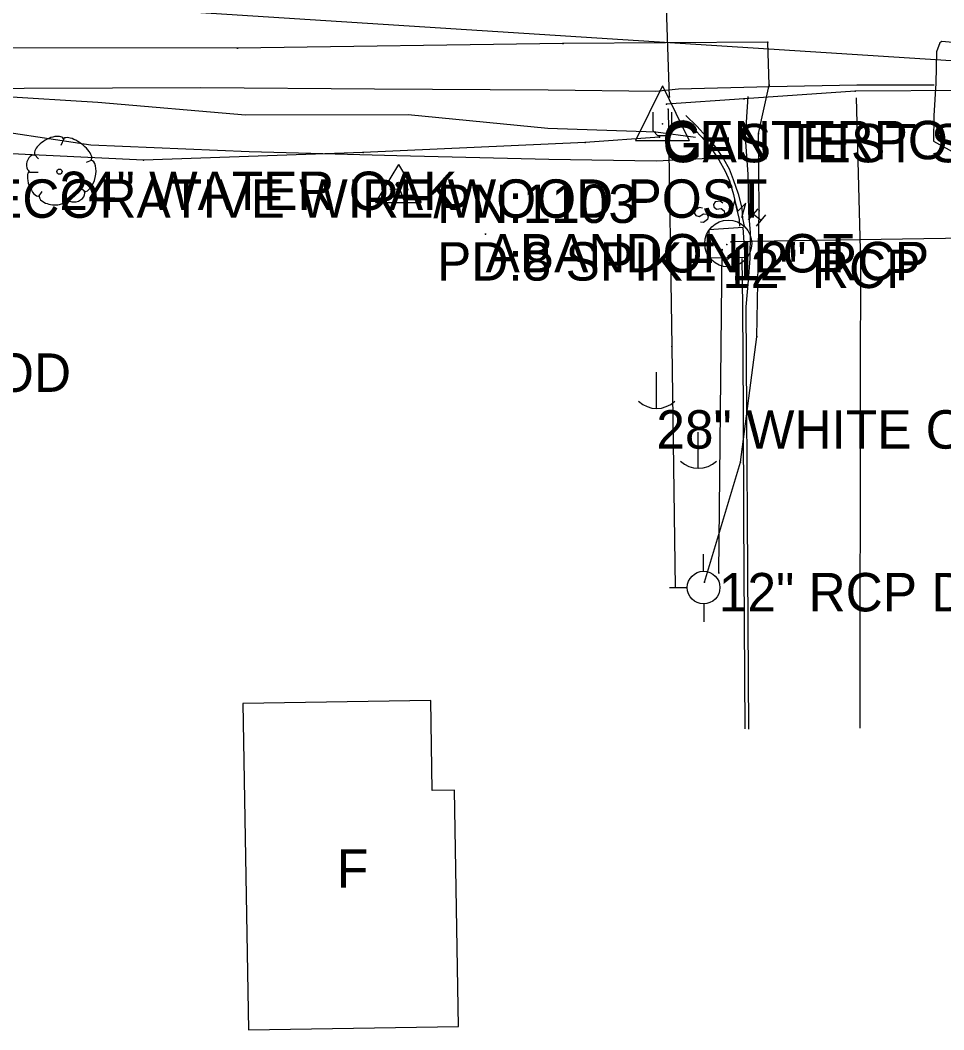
# Model space of a CAD drawing. Extents: x 1304270 to 1306561, y 1876019 to 1876752.
# Drawn here: x 1305816.1 to 1305936.2, y 1876269 to 1876400.4 of the extents above; entities that cross this region are included whole.
import ezdxf

# ---------------------------------------------------------------- set-up
doc = ezdxf.new("R2010")
doc.units = 0
for name, color, linetype in [('Default', 7, 'Continuous'), ('S_BUILDING', 7, 'Continuous'), ('S_BUILDING_ANNOT', 7, 'Continuous'), ('S_CURB', 7, 'Continuous'), ('S_DRG_PT_SYM', 7, 'Continuous'), ('S_EDGE_CONCRETE', 7, 'Continuous'), ('S_EDGE_PAVEMENT', 7, 'Continuous'), ('S_FENCE_ANNOT', 7, 'Continuous'), ('S_FIBER_OPTIC_CABLE', 7, 'Continuous'), ('S_GAS_UTILITIES', 7, 'Continuous'), ('S_MANHOLE', 7, 'Continuous'), ('S_MISC_STRUCTURES_ANNOT', 7, 'Continuous'), ('S_MSC_PT_SYM', 7, 'Continuous'), ('S_PAVEMENT_CROWN', 7, 'Continuous'), ('S_SECONDARY_CTL', 7, 'Continuous'), ('S_SECONDARY_CTL_ANNOT', 7, 'Continuous'), ('S_STORM_SEWER', 7, 'Continuous'), ('S_STORM_SEWER_ANNOT', 7, 'Continuous'), ('S_SURVEY_TEXT_ANNOT', 7, 'Continuous'), ('S_TRAILS', 7, 'Continuous'), ('S_TREE', 7, 'Continuous'), ('S_TREE_ANNOT', 7, 'Continuous'), ('S_UTILITY_POLE', 7, 'Continuous'), ('S_UTILITY_POLE_ANNOT', 7, 'Continuous'), ('S_UTL_PT_SYM', 7, 'Continuous')]:
    doc.layers.add(name, color=color, linetype=linetype)

msp = doc.modelspace()

# ---------------------------------------------------------------- linework, layer by layer
at = {"layer": 'Default'}
msp.add_line((1305473.53, 1876424.94), (1305993.25, 1876391.55), dxfattribs=at)
at = {"layer": 'S_BUILDING'}
msp.add_lwpolyline([(1305845.03, 1876311.46), (1305845.74, 1876269.01), (1305873.08, 1876269.46), (1305872.58, 1876300.2), (1305869.66, 1876300.16), (1305869.47, 1876311.86)], close=True, dxfattribs=at)
at = {"layer": 'S_CURB'}
for points in [[(1305902.26, 1876387.4), (1305903.79, 1876386.18), (1305904.8, 1876385.11), (1305906.11, 1876383.54), (1305906.97, 1876382.21), (1305907.78, 1876380.73), (1305908.35, 1876379.48), (1305908.86, 1876377.7), (1305909.26, 1876375.86), (1305909.61, 1876374.52), (1305909.64, 1876373.6)], [(1305909.96, 1876369.37), (1305910.04, 1876363.22), (1305910.11, 1876349.45), (1305910.19, 1876335.69), (1305910.27, 1876321.92), (1305910.34, 1876308.16)]]:
    msp.add_lwpolyline(points, dxfattribs=at)
at = {"layer": 'S_DRG_PT_SYM'}
msp.add_lwpolyline([(1305910.39, 1876371.51), (1305910.39, 1876371.56), (1305910.39, 1876371.51), (1305910.34, 1876371.51), (1305910.39, 1876371.51), (1305910.39, 1876371.46), (1305910.39, 1876371.51), (1305910.44, 1876371.51)], dxfattribs=at)
at = {"layer": 'S_EDGE_CONCRETE'}
msp.add_lwpolyline([(1305940.34, 1876397.25), (1305935.98, 1876397.61), (1305935.7, 1876397.43), (1305935.28, 1876396.27), (1305935.22, 1876392.2), (1305934.94, 1876387.94), (1305934.88, 1876384.67), (1305937.71, 1876383.09)], dxfattribs=at)
msp.add_lwpolyline([(1305910.11, 1876373.4), (1305905.65, 1876373.1), (1305905.71, 1876369.49), (1305910.41, 1876369.58)], close=True, dxfattribs=at)
at = {"layer": 'S_EDGE_PAVEMENT'}
for points in [[(1305613.53, 1876391.75), (1305628.13, 1876391.53), (1305636.57, 1876391.38), (1305646.7, 1876391.57), (1305664.4, 1876391.37), (1305677.09, 1876391.42), (1305689.77, 1876391.47), (1305705.71, 1876391.48), (1305716.06, 1876391.37), (1305738.42, 1876391.47), (1305752.22, 1876391.48), (1305766.03, 1876391.49), (1305779.83, 1876391.49), (1305793.63, 1876391.5), (1305816.58, 1876391.56), (1305839.54, 1876391.62), (1305862.15, 1876391.47), (1305884.77, 1876391.33), (1305898.76, 1876391.18), (1305901.73, 1876391.47), (1305913.59, 1876391.75), (1305924.92, 1876391.98), (1305934.98, 1876391.98)], [(1305910.73, 1876390.48), (1305910.4, 1876385.14), (1305910.72, 1876380.38), (1305910.82, 1876375.33), (1305911.03, 1876372.76), (1305910.98, 1876369.39), (1305910.79, 1876366.53), (1305910.47, 1876363.11), (1305910.56, 1876349.36), (1305910.65, 1876335.62), (1305910.74, 1876321.87), (1305910.83, 1876308.13)], [(1305902.68, 1876387.99), (1305904.09, 1876386.6), (1305905.37, 1876385.2), (1305906.55, 1876383.89), (1305907.58, 1876382.36), (1305908.3, 1876381.05), (1305908.85, 1876379.67), (1305909.47, 1876377.81), (1305909.94, 1876375.93), (1305910.06, 1876374.57), (1305910.25, 1876373.61)]]:
    msp.add_lwpolyline(points, dxfattribs=at)
at = {"layer": 'S_FIBER_OPTIC_CABLE'}
for p, q in [((1305844.31, 1876396.74), (1305789.79, 1876396.84)), ((1305886.69, 1876397.37), (1305844.31, 1876396.74)), ((1305913.35, 1876397.55), (1305886.69, 1876397.37)), ((1305913.53, 1876391.96), (1305913.35, 1876397.55)), ((1305912.14, 1876385.64), (1305913.53, 1876391.96)), ((1305912.19, 1876375.58), (1305912.14, 1876385.64)), ((1305911.92, 1876359.21), (1305912.19, 1876375.58)), ((1305909.78, 1876342.89), (1305911.92, 1876359.21)), ((1305905.08, 1876327.25), (1305909.78, 1876342.89))]:
    msp.add_line(p, q, dxfattribs=at)
at = {"layer": 'S_GAS_UTILITIES'}
for p, q in [((1305900.53, 1876390.42), (1305899.88, 1876409.72)), ((1305910.24, 1876390.16), (1305900.15, 1876389.47)), ((1305924.69, 1876391.17), (1305910.24, 1876390.16)), ((1305943.66, 1876391.26), (1305924.69, 1876391.17)), ((1305900.37, 1876388.82), (1305900.85, 1876357.93)), ((1305899.24, 1876385.19), (1305889.57, 1876384.49)), ((1305889.57, 1876384.49), (1305860.69, 1876383.2)), ((1305832.09, 1876382.18), (1305808.21, 1876383.3)), ((1305860.69, 1876383.2), (1305832.09, 1876382.18)), ((1305900.85, 1876357.93), (1305901.27, 1876326.56))]:
    msp.add_line(p, q, dxfattribs=at)
at = {"layer": 'S_MANHOLE'}
for p, q in [((1305903.86, 1876375.64), (1305903.78, 1876375.25)), ((1305904.4, 1876376.03), (1305903.86, 1876375.64)), ((1305904.83, 1876375.95), (1305904.4, 1876376.03)), ((1305910.84, 1876374.4), (1305912.08, 1876375.87)), ((1305903.78, 1876375.25), (1305903.98, 1876374.98)), ((1305903.98, 1876374.98), (1305904.4, 1876374.86)), ((1305904.4, 1876374.86), (1305904.95, 1876375.21)), ((1305904.95, 1876375.21), (1305905.41, 1876375.14)), ((1305905.49, 1876374.44), (1305904.95, 1876374.05)), ((1305905.41, 1876375.14), (1305905.57, 1876374.86)), ((1305905.57, 1876374.86), (1305905.49, 1876374.44)), ((1305911.49, 1876375.17), (1305912.46, 1876374.36)), ((1305913.04, 1876375.06), (1305911.8, 1876373.59)), ((1305904.95, 1876374.05), (1305904.56, 1876374.13))]:
    msp.add_line(p, q, dxfattribs=at)
for points in [[(1305907.5, 1876376.57), (1305907.15, 1876376.84), (1305906.5, 1876376.76), (1305906.26, 1876376.41), (1305906.3, 1876376.1), (1305906.65, 1876375.79), (1305907.27, 1876375.91), (1305907.66, 1876375.6), (1305907.7, 1876375.29), (1305907.43, 1876374.9), (1305906.81, 1876374.83), (1305906.46, 1876375.1)], [(1305909.94, 1876374.71), (1305910.49, 1876376.57), (1305909.44, 1876375.56), (1305909.05, 1876377), (1305908.51, 1876375.14)]]:
    msp.add_lwpolyline(points, dxfattribs=at)
msp.add_circle((1305908.19, 1876371.34), 3.05, dxfattribs=at)
at = {"layer": 'S_MSC_PT_SYM'}
for points in [[(1305899.64, 1876386.9), (1305899.64, 1876386.95), (1305899.64, 1876386.9), (1305899.59, 1876386.9), (1305899.64, 1876386.9), (1305899.64, 1876386.85), (1305899.64, 1876386.9), (1305899.69, 1876386.9)], [(1305876.61, 1876372.57), (1305876.61, 1876372.62), (1305876.61, 1876372.57), (1305876.56, 1876372.57), (1305876.61, 1876372.57), (1305876.61, 1876372.52), (1305876.61, 1876372.57), (1305876.66, 1876372.57)]]:
    msp.add_lwpolyline(points, dxfattribs=at)
at = {"layer": 'S_PAVEMENT_CROWN'}
msp.add_lwpolyline([(1305924.84, 1876390.29), (1305925.4, 1876368.9), (1305925.37, 1876353.74), (1305925.35, 1876338.58), (1305925.32, 1876323.41), (1305925.3, 1876308.25)], dxfattribs=at)
at = {"layer": 'S_SECONDARY_CTL'}
for p, q in [((1305865.29, 1876381.62), (1305862.28, 1876376.66)), ((1305865.29, 1876381.62), (1305868.24, 1876376.66)), ((1305862.28, 1876376.66), (1305868.24, 1876376.66))]:
    msp.add_line(p, q, dxfattribs=at)
for radius in [0.311, 0.183, 0.103]:
    msp.add_circle((1305865.29, 1876379.01), radius, dxfattribs=at)
at = {"layer": 'S_STORM_SEWER'}
for p, q in [((1305940.67, 1876372.04), (1305908.55, 1876371.55)), ((1305906.97, 1876328.46), (1305907.41, 1876370.54))]:
    msp.add_line(p, q, dxfattribs=at)
at = {"layer": 'S_TRAILS'}
for points in [[(1305709.54, 1876384.24), (1305732.29, 1876386.54), (1305746.02, 1876389.59), (1305756.26, 1876389.31), (1305771.56, 1876390.66), (1305791.13, 1876390.21), (1305813.54, 1876390.5), (1305826.15, 1876389.73), (1305845.37, 1876388.08), (1305866.53, 1876388.14), (1305884.73, 1876386.34), (1305898.77, 1876385.87), (1305903.92, 1876385.18)], [(1305708.86, 1876378.69), (1305720.67, 1876379.49), (1305732.85, 1876380.75), (1305740.78, 1876380.6), (1305750.95, 1876381.02), (1305756.14, 1876382.45), (1305771.5, 1876385.18), (1305791.31, 1876385.39), (1305813.73, 1876385.91), (1305825.25, 1876384.17), (1305845.86, 1876383.31), (1305865.08, 1876382.79), (1305884.86, 1876382.31), (1305898.84, 1876382.09), (1305905.66, 1876382.44)]]:
    msp.add_lwpolyline(points, dxfattribs=at)
at = {"layer": 'S_TREE'}
for p, q in [((1305821.71, 1876384.94), (1305821.33, 1876384.08)), ((1305817.92, 1876382.92), (1305818.42, 1876382.34)), ((1305825.28, 1876382.15), (1305824.62, 1876381.88)), ((1305817.26, 1876380.6), (1305818.38, 1876380.6)), ((1305824.5, 1876378.04), (1305824.04, 1876378.47)), ((1305818.42, 1876377.42), (1305818.89, 1876378.12)), ((1305822.1, 1876377.15), (1305822.02, 1876377.92))]:
    msp.add_line(p, q, dxfattribs=at)
msp.add_circle((1305821.16, 1876380.69), 0.341, dxfattribs=at)
for centre, major_axis, ratio, start_param, end_param in [((1305819.82, 1876383.89), (1.86, 1.08), 0.471018, 0, 3.141593), ((1305823.47, 1876383.57), (-1.81, 1.36), 0.405113, 3.141593, 6.283186), ((1305817.59, 1876381.78), (0.31, 1.03), 0.646762, 0, 3.141593), ((1305824.83, 1876380.16), (0.46, 2.04), 0.482994, 3.141593, 6.283185), ((1305817.89, 1876379.13), (-0.61, 1.6), 0.420543, 6.283185, 9.424777), ((1305820.35, 1876377.35), (-1.83, 0.19), 0.529943, 0, 3.141593), ((1305823.31, 1876377.64), (1.09, 0.46), 0.711534, 3.141592, 6.283185)]:
    msp.add_ellipse(centre, major_axis=major_axis, ratio=ratio, start_param=start_param, end_param=end_param, dxfattribs=at)
at = {"layer": 'S_UTILITY_POLE'}
for p, q in [((1305899.62, 1876391.84), (1305896.1, 1876384.75)), ((1305899.62, 1876391.84), (1305903.11, 1876384.75)), ((1305898.42, 1876385.99), (1305898.42, 1876388.43)), ((1305900.79, 1876388.43), (1305900.79, 1876385.99)), ((1305896.1, 1876384.75), (1305903.11, 1876384.75)), ((1305899.04, 1876385.33), (1305898.42, 1876385.99)), ((1305900.24, 1876385.33), (1305899.04, 1876385.33)), ((1305900.79, 1876385.99), (1305900.24, 1876385.33)), ((1305898.82, 1876354.58), (1305898.82, 1876349.85)), ((1305904.24, 1876346.79), (1305904.24, 1876342.06)), ((1305904.98, 1876328.67), (1305904.98, 1876330.92)), ((1305902.88, 1876326.54), (1305900.56, 1876326.54)), ((1305905.05, 1876322.12), (1305905.05, 1876324.45))]:
    msp.add_line(p, q, dxfattribs=at)
msp.add_circle((1305904.98, 1876326.56), 2.13, dxfattribs=at)
for centre in [(1305898.88, 1876353.28), (1305904.31, 1876345.49)]:
    msp.add_arc(centre, 3.41, 226.3972, 313.6028, dxfattribs=at)
at = {"layer": 'S_UTL_PT_SYM'}
for points in [[(1305844.31, 1876396.74), (1305844.31, 1876396.79), (1305844.31, 1876396.74), (1305844.26, 1876396.74), (1305844.31, 1876396.74), (1305844.31, 1876396.69), (1305844.31, 1876396.74), (1305844.36, 1876396.74)], [(1305886.69, 1876397.37), (1305886.69, 1876397.42), (1305886.69, 1876397.37), (1305886.64, 1876397.37), (1305886.69, 1876397.37), (1305886.69, 1876397.32), (1305886.69, 1876397.37), (1305886.74, 1876397.37)], [(1305913.35, 1876397.55), (1305913.35, 1876397.6), (1305913.35, 1876397.55), (1305913.3, 1876397.55), (1305913.35, 1876397.55), (1305913.35, 1876397.5), (1305913.35, 1876397.55), (1305913.4, 1876397.55)], [(1305913.53, 1876391.96), (1305913.53, 1876392.01), (1305913.53, 1876391.96), (1305913.48, 1876391.96), (1305913.53, 1876391.96), (1305913.53, 1876391.91), (1305913.53, 1876391.96), (1305913.58, 1876391.96)], [(1305900.53, 1876390.42), (1305900.53, 1876390.47), (1305900.53, 1876390.42), (1305900.48, 1876390.42), (1305900.53, 1876390.42), (1305900.53, 1876390.37), (1305900.53, 1876390.42), (1305900.58, 1876390.42)], [(1305910.24, 1876390.16), (1305910.24, 1876390.21), (1305910.24, 1876390.16), (1305910.19, 1876390.16), (1305910.24, 1876390.16), (1305910.24, 1876390.11), (1305910.24, 1876390.16), (1305910.29, 1876390.16)], [(1305924.69, 1876391.17), (1305924.69, 1876391.22), (1305924.69, 1876391.17), (1305924.64, 1876391.17), (1305924.69, 1876391.17), (1305924.69, 1876391.12), (1305924.69, 1876391.17), (1305924.74, 1876391.17)], [(1305900.15, 1876389.47), (1305900.15, 1876389.52), (1305900.15, 1876389.47), (1305900.1, 1876389.47), (1305900.15, 1876389.47), (1305900.15, 1876389.42), (1305900.15, 1876389.47), (1305900.2, 1876389.47)], [(1305900.37, 1876388.82), (1305900.37, 1876388.87), (1305900.37, 1876388.82), (1305900.32, 1876388.82), (1305900.37, 1876388.82), (1305900.37, 1876388.77), (1305900.37, 1876388.82), (1305900.42, 1876388.82)], [(1305899.24, 1876385.19), (1305899.24, 1876385.24), (1305899.24, 1876385.19), (1305899.19, 1876385.19), (1305899.24, 1876385.19), (1305899.24, 1876385.14), (1305899.24, 1876385.19), (1305899.29, 1876385.19)], [(1305912.14, 1876385.64), (1305912.14, 1876385.69), (1305912.14, 1876385.64), (1305912.09, 1876385.64), (1305912.14, 1876385.64), (1305912.14, 1876385.59), (1305912.14, 1876385.64), (1305912.19, 1876385.64)], [(1305889.57, 1876384.49), (1305889.57, 1876384.54), (1305889.57, 1876384.49), (1305889.52, 1876384.49), (1305889.57, 1876384.49), (1305889.57, 1876384.44), (1305889.57, 1876384.49), (1305889.62, 1876384.49)], [(1305832.09, 1876382.18), (1305832.09, 1876382.23), (1305832.09, 1876382.18), (1305832.04, 1876382.18), (1305832.09, 1876382.18), (1305832.09, 1876382.13), (1305832.09, 1876382.18), (1305832.14, 1876382.18)], [(1305860.69, 1876383.2), (1305860.69, 1876383.25), (1305860.69, 1876383.2), (1305860.64, 1876383.2), (1305860.69, 1876383.2), (1305860.69, 1876383.15), (1305860.69, 1876383.2), (1305860.74, 1876383.2)], [(1305912.19, 1876375.58), (1305912.19, 1876375.63), (1305912.19, 1876375.58), (1305912.14, 1876375.58), (1305912.19, 1876375.58), (1305912.19, 1876375.53), (1305912.19, 1876375.58), (1305912.24, 1876375.58)], [(1305908.55, 1876371.55), (1305908.55, 1876371.6), (1305908.55, 1876371.55), (1305908.5, 1876371.55), (1305908.55, 1876371.55), (1305908.55, 1876371.5), (1305908.55, 1876371.55), (1305908.6, 1876371.55)], [(1305907.41, 1876370.54), (1305907.41, 1876370.59), (1305907.41, 1876370.54), (1305907.36, 1876370.54), (1305907.41, 1876370.54), (1305907.41, 1876370.49), (1305907.41, 1876370.54), (1305907.46, 1876370.54)], [(1305907.99, 1876371.22), (1305907.99, 1876371.27), (1305907.99, 1876371.22), (1305907.94, 1876371.22), (1305907.99, 1876371.22), (1305907.99, 1876371.17), (1305907.99, 1876371.22), (1305908.04, 1876371.22)], [(1305911.92, 1876359.21), (1305911.92, 1876359.26), (1305911.92, 1876359.21), (1305911.87, 1876359.21), (1305911.92, 1876359.21), (1305911.92, 1876359.16), (1305911.92, 1876359.21), (1305911.97, 1876359.21)], [(1305900.85, 1876357.93), (1305900.85, 1876357.98), (1305900.85, 1876357.93), (1305900.8, 1876357.93), (1305900.85, 1876357.93), (1305900.85, 1876357.88), (1305900.85, 1876357.93), (1305900.9, 1876357.93)], [(1305909.78, 1876342.89), (1305909.78, 1876342.94), (1305909.78, 1876342.89), (1305909.73, 1876342.89), (1305909.78, 1876342.89), (1305909.78, 1876342.84), (1305909.78, 1876342.89), (1305909.83, 1876342.89)], [(1305906.97, 1876328.46), (1305906.97, 1876328.51), (1305906.97, 1876328.46), (1305906.92, 1876328.46), (1305906.97, 1876328.46), (1305906.97, 1876328.41), (1305906.97, 1876328.46), (1305907.02, 1876328.46)], [(1305905.08, 1876327.25), (1305905.08, 1876327.3), (1305905.08, 1876327.25), (1305905.03, 1876327.25), (1305905.08, 1876327.25), (1305905.08, 1876327.2), (1305905.08, 1876327.25), (1305905.14, 1876327.25)], [(1305901.27, 1876326.56), (1305901.27, 1876326.61), (1305901.27, 1876326.56), (1305901.22, 1876326.56), (1305901.27, 1876326.56), (1305901.27, 1876326.51), (1305901.27, 1876326.56), (1305901.32, 1876326.56)]]:
    msp.add_lwpolyline(points, dxfattribs=at)

# ---------------------------------------------------------------- texts
at = {"layer": 'S_BUILDING_ANNOT'}
msp.add_text('F', height=5, dxfattribs=at).set_placement((1305857.26, 1876287.49))
at = {"layer": 'S_FENCE_ANNOT'}
for s, p in [("2.5' DECORATIVE WIRE/WOOD POST", (1305794.61, 1876374.68)), ("5' CHAINLINK 3 BARB/MTL POST GOOD", (1305696.93, 1876352.03))]:
    msp.add_text(s, height=5, dxfattribs=at).set_placement(p)
at = {"layer": 'S_MISC_STRUCTURES_ANNOT'}
msp.add_text('GAS TEST STATION', height=5, dxfattribs=at).set_placement((1305899.64, 1876381.9))
at = {"layer": 'S_SECONDARY_CTL'}
msp.add_text('TV', height=1.5, rotation=360, dxfattribs=at).set_placement((1305864.08, 1876376.99))
at = {"layer": 'S_SECONDARY_CTL_ANNOT'}
for s, p in [('PN:1103', (1305870.29, 1876374.01)), ('PD:8 SPIKE', (1305870.29, 1876366.51))]:
    msp.add_text(s, height=5, dxfattribs=at).set_placement(p)
at = {"layer": 'S_STORM_SEWER_ANNOT'}
for s, p in [('12" RCP', (1305908.55, 1876366.55)), ('12" RCP', (1305907.41, 1876365.54)), ('12" RCP DIRECTION ONLY', (1305906.97, 1876323.46))]:
    msp.add_text(s, height=5, dxfattribs=at).set_placement(p)
at = {"layer": 'S_SURVEY_TEXT_ANNOT'}
msp.add_text('ABANDON LOT', height=5, dxfattribs=at).set_placement((1305876.61, 1876367.57))
at = {"layer": 'S_TREE_ANNOT'}
msp.add_text('24" WATER OAK', height=5, dxfattribs=at).set_placement((1305821.16, 1876375.69))
at = {"layer": 'S_UTILITY_POLE_ANNOT'}
for s, p in [('CENTERPOINT ENTERGY', (1305899.62, 1876382.3)), ('28" WHITE OAK', (1305898.83, 1876344.64))]:
    msp.add_text(s, height=5, dxfattribs=at).set_placement(p)

doc.saveas('drawing.dxf')
